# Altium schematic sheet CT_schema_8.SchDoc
size 277 x 170 mm
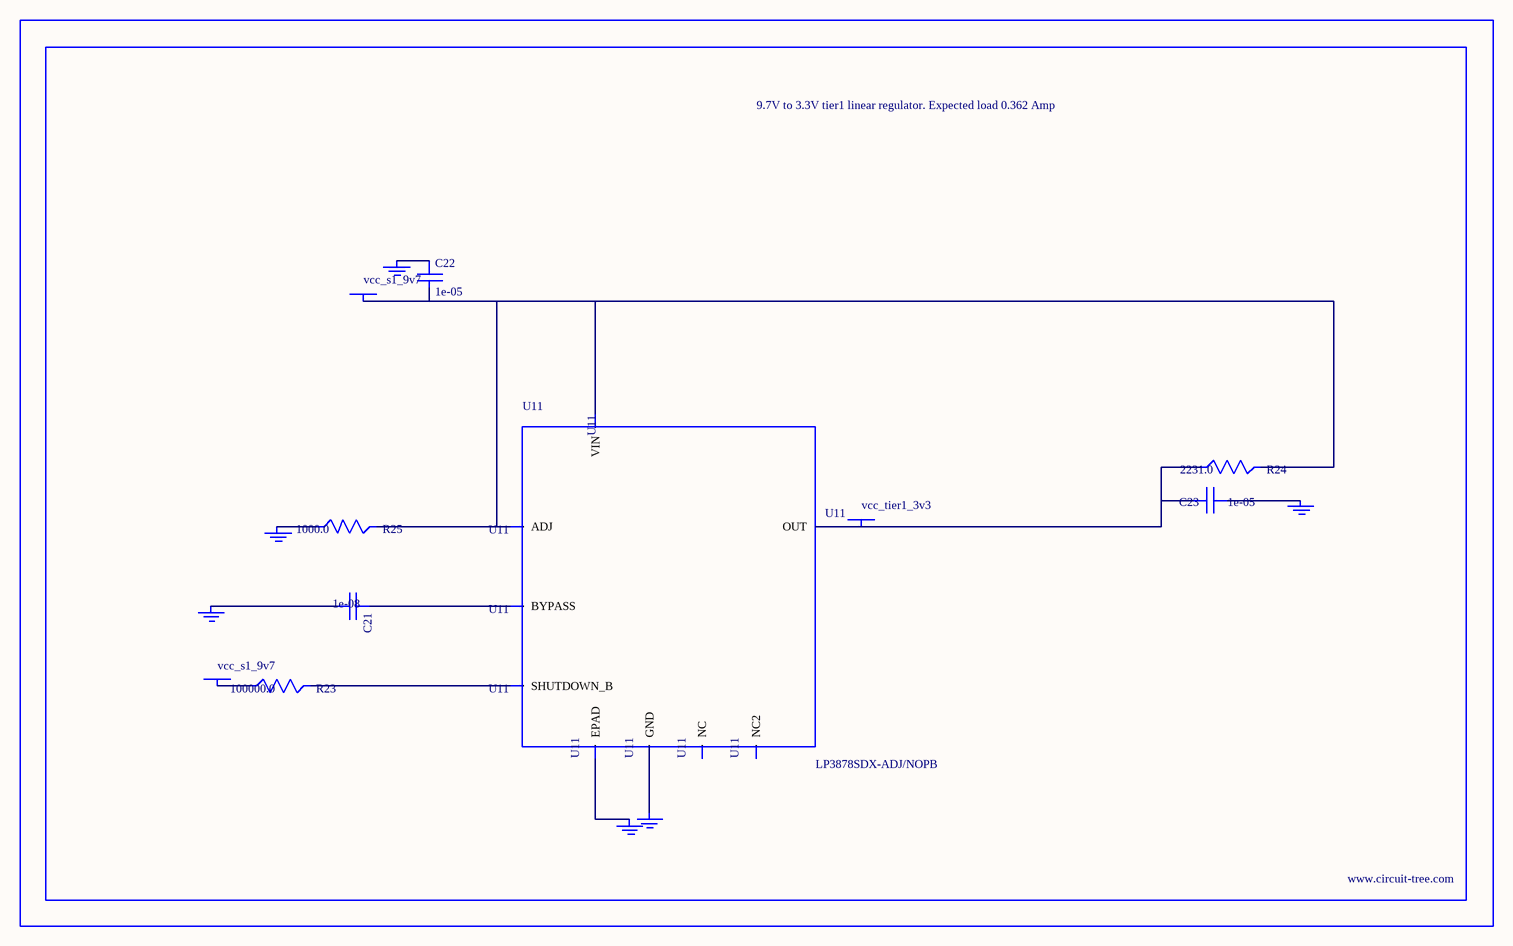
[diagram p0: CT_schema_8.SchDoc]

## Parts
BORDER7  (no value)
C21  1e-08  [C0402]
C22  1e-05  [C1206]
C23  1e-05  [C1210]
GND_INSTANCE_7_0  (no value)
GND_INSTANCE_7_1  (no value)
GND_INSTANCE_7_2  (no value)
GND_INSTANCE_7_3  (no value)
GND_INSTANCE_7_4  (no value)
GND_INSTANCE_7_5  (no value)
POWER_INSTANCE_7_0  vcc_s1_9v7
POWER_INSTANCE_7_1  vcc_s1_9v7
POWER_INSTANCE_7_2  vcc_tier1_3v3
R23  100000.0  [R0603]
R24  2231.0  [R0603]
R25  1000.0  [R0603]
U11  LP3878SDX-ADJ/NOPB  [WSON-8]

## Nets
NetC21_1: C21.1 U11.1(BYPASS)
NetC21_2: C21.2 GND_INSTANCE_7_0.0(GND)
NetC22_1: C22.1 GND_INSTANCE_7_1.0(GND)
NetC22_2: C22.2 POWER_INSTANCE_7_0.0(PWR) R24.2 R25.2 U11.4(VIN) U11.6(ADJ)
NetC23_1: C23.1 GND_INSTANCE_7_2.0(GND)
NetC23_2: C23.2 POWER_INSTANCE_7_2.0(PWR) R24.1 U11.5(OUT)
NetGND_INSTANCE_7_3_0: GND_INSTANCE_7_3.0(GND) R25.1
NetGND_INSTANCE_7_4_0: GND_INSTANCE_7_4.0(GND) U11.PAD(EPAD)
NetGND_INSTANCE_7_5_0: GND_INSTANCE_7_5.0(GND) U11.3(GND)
NetPOWER_INSTANCE_7_1_0: POWER_INSTANCE_7_1.0(PWR) R23.1
NetR23_2: R23.2 U11.8(SHUTDOWN_B)

Not connected (* = marked no-connect by the designer): U11 2(NC) 7(NC2)

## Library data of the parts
BORDER7 = BORDER_PAGE7
C21 = C0402C103K3RAC
C22 = C1206C106K3RACTU
C23 = GRM32DR61E106MA12L
GND_INSTANCE_7_0-GND_INSTANCE_7_5 = GND
POWER_INSTANCE_7_0-POWER_INSTANCE_7_2 = PWR
R23 = RC0603JR-07100KL
R24 = R24
R25 = RC0603JR-071KL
